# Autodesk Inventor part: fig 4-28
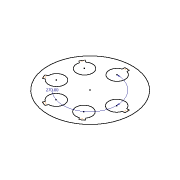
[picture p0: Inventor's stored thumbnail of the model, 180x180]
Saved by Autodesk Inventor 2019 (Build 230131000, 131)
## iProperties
Created: 2004-05
Part Number: fig 4-28
Document SubType Name: Modeling
Designer: CADCIM Technologies
Manufacturer: Standard
Standards Organization: Custom
Density: 1 g/cm^3
Material: Generic
Appearance: Default
Author: CADCIM Technologies
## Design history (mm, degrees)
sketch "Sketch2"
  geometry: L1 (0.73, 11.049)-(0.73, 11.828); L2 (0.73, 11.828)-(-0.73, 11.828); L3 (-0.73, 11.828)-(-0.73, 11.006); L4 (-0.152, 11.061)-(0.73, 11.828); L5 (0.152, 11.061)-(-0.73, 11.828); L6 (-8.51, 7.085)-(-9.14, 7.543); L7 (-9.14, 7.543)-(-9.998, 6.362); L8 (-9.998, 6.362)-(-9.333, 5.879); L9 (-9.038, 6.378)-(-9.14, 7.543); L10 (-8.859, 6.625)-(-9.998, 6.362); L11 (-10.734, -2.72)-(-11.474, -2.961); L12 (-11.474, -2.961)-(-11.023, -4.349); L13 (-11.023, -4.349)-(-10.242, -4.095); L14 (-10.472, -3.563)-(-11.474, -2.961); L15 (-10.566, -3.273)-(-11.023, -4.349); L16 (-4.108, -10.283)-(-4.349, -11.023); L17 (-4.349, -11.023)-(-2.961, -11.474); L18 (-2.961, -11.474)-(-2.707, -10.693); L19 (-3.273, -10.566)-(-4.349, -11.023); L20 (-3.563, -10.472)-(-2.961, -11.474); L21 (5.904, -9.368)-(6.362, -9.998); L22 (6.362, -9.998)-(7.543, -9.14); L23 (7.543, -9.14)-(7.06, -8.475); L24 (6.625, -8.859)-(6.362, -9.998); L25 (6.378, -9.038)-(7.543, -9.14); L26 (11.049, -0.73)-(11.828, -0.73); L27 (11.828, -0.73)-(11.828, 0.73); L28 (11.828, 0.73)-(11.006, 0.73); L29 (11.061, 0.152)-(11.828, -0.73); L30 (11.061, -0.152)-(11.828, 0.73); C1 r 13.473 at (0, 0); A1 r 2.558 centre (0.072, 8.577) between (-0.73, 11.006) and (0.73, 11.049); A2 r 2.558 centre (-6.897, 5.1) between (-9.333, 5.879) and (-8.51, 7.085); A3 r 2.558 centre (-8.18, -2.582) between (-10.242, -4.095) and (-10.734, -2.72); A4 r 2.558 centre (-2.719, -8.135) between (-2.707, -10.693) and (-4.108, -10.283); A5 r 2.558 centre (4.983, -6.981) between (7.06, -8.475) and (5.904, -9.368); A6 r 2.558 centre (8.577, -0.072) between (11.006, 0.73) and (11.049, -0.73); 6 further points
  constraints: 60 end point, 12 point on circle, 7 centre point, 2 coincident, 1 parallel, 70 other
  dimensions: "d6" = 270 deg dimension on point (0, 0) A1.centre A6.centre
